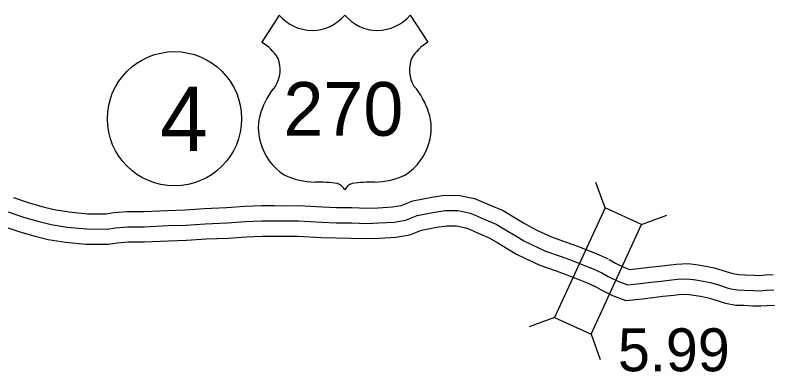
# Model space of a CAD drawing. Extents: x -83719 to 153526, y -11835 to 11446.
# Drawn here: x -4104.1 to -3856.7, y -3407.1 to -3290.1 of the extents above; entities that cross this region are included whole.
import ezdxf

# ---------------------------------------------------------------- set-up
doc = ezdxf.new("R2010")
doc.units = 0
for name, color, linetype in [('Level 15', 7, 'Continuous'), ('Level 20', 7, 'Continuous'), ('Level 22', 7, 'Continuous'), ('Level 27', 7, 'Continuous'), ('Level 58', 7, 'Continuous'), ('Level 59', 7, 'Continuous')]:
    doc.layers.add(name, color=color, linetype=linetype)

msp = doc.modelspace()

# ---------------------------------------------------------------- linework, layer by layer
at = {"layer": 'Level 15'}
for points in [[(-4104.59, -3349.95), (-4099.83, -3351.58), (-4095.29, -3352.89), (-4091.28, -3353.89), (-4086.33, -3354.67), (-4080.34, -3355.25), (-4074.22, -3355.26), (-4071.75, -3354.9), (-4067.46, -3354.51), (-4061.85, -3354.51), (-4054.13, -3354.15), (-4048.36, -3353.97), (-4042.06, -3353.53), (-4034.84, -3353.23), (-4028.8, -3352.79), (-4023.32, -3352.58), (-4019.07, -3352.6), (-4015.79, -3352.62), (-4011.11, -3352.59), (-4003.35, -3353), (-3998.76, -3353.2), (-3993.72, -3353.24), (-3988.81, -3353.41), (-3985.08, -3353.3), (-3980.44, -3353.02), (-3977.56, -3352.51), (-3973.78, -3350.98), (-3967.48, -3349.79), (-3963.35, -3349.21), (-3958.35, -3349.23), (-3953.54, -3350.3), (-3951.43, -3351.09), (-3948.43, -3352.42), (-3944.19, -3354.19), (-3940.79, -3356.24), (-3937.43, -3358.25), (-3934.94, -3359.71), (-3932.71, -3360.86), (-3928.36, -3362.86), (-3923.48, -3364.59), (-3919.79, -3365.91), (-3916.24, -3367.29), (-3912.71, -3368.67), (-3909.76, -3370.03)], [(-4108.06, -3359.33), (-4102.84, -3361.12), (-4097.89, -3362.55), (-4093.27, -3363.7), (-4087.59, -3364.59), (-4080.84, -3365.25), (-4073.49, -3365.27), (-4070.57, -3364.83), (-4067.01, -3364.51), (-4061.61, -3364.51), (-4053.75, -3364.14), (-4047.86, -3363.96), (-4041.5, -3363.51), (-4034.27, -3363.22), (-4028.25, -3362.78), (-4023.14, -3362.58), (-4019.12, -3362.6), (-4015.8, -3362.62), (-4011.35, -3362.6), (-4003.83, -3362.99), (-3999.02, -3363.2), (-3993.92, -3363.24), (-3988.83, -3363.41), (-3984.63, -3363.29), (-3979.28, -3362.97), (-3974.78, -3362.18), (-3970.94, -3360.62), (-3965.86, -3359.66), (-3962.67, -3359.21), (-3959.47, -3359.22), (-3956.39, -3359.91), (-3955.22, -3360.35), (-3952.39, -3361.61), (-3948.72, -3363.14), (-3945.94, -3364.82), (-3942.52, -3366.86), (-3939.77, -3368.47), (-3937.1, -3369.85), (-3932.13, -3372.14), (-3926.83, -3374.01), (-3923.28, -3375.28), (-3919.87, -3376.6), (-3916.63, -3377.87), (-3913.95, -3379.11)], [(-3909.36, -3370.24), (-3907.32, -3371.41), (-3904.4, -3372.9), (-3902.71, -3373.5), (-3899.75, -3373.18), (-3896.29, -3372.77), (-3892.96, -3372.39), (-3889.45, -3371.98), (-3887.38, -3371.73), (-3883.55, -3371.6), (-3880.28, -3371.99), (-3877.72, -3372.43), (-3875.02, -3372.96), (-3872.15, -3373.81), (-3868.92, -3374.87), (-3866.89, -3375.22), (-3864.84, -3375.28), (-3861.94, -3375.44), (-3860.05, -3375.47), (-3858.33, -3375.33), (-3855.68, -3375.19)], [(-3914.35, -3378.9), (-3912.09, -3380.21), (-3908.37, -3382.1), (-3903.9, -3383.69), (-3898.61, -3383.11), (-3895.14, -3382.7), (-3891.82, -3382.32), (-3888.27, -3381.91), (-3886.61, -3381.71), (-3883.98, -3381.62), (-3881.71, -3381.89), (-3879.52, -3382.27), (-3877.41, -3382.68), (-3875.14, -3383.36), (-3871.33, -3384.61), (-3867.88, -3385.19), (-3865.27, -3385.27), (-3862.3, -3385.44), (-3859.72, -3385.48), (-3857.65, -3385.31), (-3855.29, -3385.18)]]:
    msp.add_lwpolyline(points, dxfattribs=at)
at = {"layer": 'Level 20'}
for p, q in [((-3910.76, -3353.27), (-3913.81, -3345.02)), ((-3898.77, -3358.8), (-3890.52, -3355.75)), ((-3927.34, -3389.23), (-3935.59, -3392.28)), ((-3915.35, -3394.76), (-3912.31, -3403.02))]:
    msp.add_line(p, q, dxfattribs=at)
msp.add_lwpolyline([(-3910.76, -3353.27), (-3927.34, -3389.23), (-3915.35, -3394.76), (-3898.77, -3358.8)], close=True, dxfattribs=at)
at = {"layer": 'Level 22'}
for p, q in [((-4017.49, -3290.15), (-4023.26, -3299.07)), ((-3974.6, -3290.15), (-3968.83, -3299.07))]:
    msp.add_line(p, q, dxfattribs=at)
for centre, radius, start, end in [((-4006.75, -3281.11), 14.04, 220.075, 319.6701), ((-3985.34, -3281.11), 14.04, 220.3299, 319.925), ((-4030.8, -3312.02), 14.99, 30.7809, 59.9883), ((-3961.29, -3312.02), 14.99, 120.0117, 149.2191), ((-4027.5, -3308.07), 10.28, 328.8105, 21.2108), ((-3964.59, -3308.07), 10.28, 158.7892, 211.1895), ((-4000.63, -3329.13), 23.97, 138.9565, 162.6913), ((-3991.46, -3329.13), 23.97, 17.3087, 41.0435), ((-4008.55, -3327.17), 15.84, 160.9576, 197.3819), ((-3983.54, -3327.17), 15.84, 342.6181, 19.0424), ((-4005.97, -3327.12), 18.33, 195.1074, 237.1312), ((-3986.12, -3327.12), 18.33, 302.8688, 344.8926), ((-4005.63, -3321.35), 23.53, 244.0771, 269.5779), ((-3986.46, -3321.35), 23.53, 270.4221, 295.9229), ((-4005.08, -3387.99), 43.11, 81.1942, 90.9539), ((-3999.69, -3349.34), 4.13, 28.0342, 72.9864), ((-3992.4, -3349.34), 4.13, 107.0136, 151.9658), ((-3987.01, -3387.99), 43.11, 89.0461, 98.8058)]:
    msp.add_arc(centre, radius, start, end, dxfattribs=at)
at = {"layer": 'Level 27'}
msp.add_circle((-4051.84, -3324.13), 22, dxfattribs=at)
at = {"layer": 'Level 59'}
for points in [[(-4106.33, -3354.64), (-4101.34, -3356.35), (-4096.59, -3357.72), (-4092.27, -3358.8), (-4086.96, -3359.63), (-4080.59, -3360.25), (-4073.86, -3360.26), (-4071.16, -3359.86), (-4067.23, -3359.51), (-4061.73, -3359.51), (-4053.94, -3359.14), (-4048.11, -3358.97), (-4041.78, -3358.52), (-4034.55, -3358.23), (-4028.53, -3357.78), (-4023.23, -3357.58), (-4019.1, -3357.6), (-4015.8, -3357.62), (-4011.23, -3357.59), (-4003.59, -3358), (-3998.89, -3358.2), (-3993.82, -3358.24), (-3988.82, -3358.41), (-3984.86, -3358.29), (-3979.86, -3357.99), (-3976.17, -3357.35), (-3972.36, -3355.8), (-3966.67, -3354.72), (-3963.01, -3354.21), (-3958.91, -3354.22), (-3954.97, -3355.11), (-3953.33, -3355.72), (-3950.41, -3357.02), (-3946.45, -3358.67), (-3943.36, -3360.53), (-3939.97, -3362.55), (-3937.35, -3364.09), (-3934.9, -3365.36), (-3930.24, -3367.5), (-3925.15, -3369.3), (-3921.54, -3370.59), (-3918.05, -3371.95), (-3914.67, -3373.27), (-3911.86, -3374.57)], [(-3911.86, -3374.57), (-3909.71, -3375.81), (-3906.38, -3377.5), (-3903.3, -3378.6), (-3899.18, -3378.14), (-3895.72, -3377.73), (-3892.39, -3377.36), (-3888.86, -3376.94), (-3887, -3376.72), (-3883.76, -3376.61), (-3880.99, -3376.94), (-3878.62, -3377.35), (-3876.22, -3377.82), (-3873.64, -3378.58), (-3870.13, -3379.74), (-3867.39, -3380.21), (-3865.05, -3380.28), (-3862.12, -3380.44), (-3859.88, -3380.48), (-3857.99, -3380.32), (-3855.49, -3380.19)]]:
    msp.add_lwpolyline(points, dxfattribs=at)

# ---------------------------------------------------------------- texts
at = {"layer": 'Level 22'}
msp.add_text('270', height=17.6, dxfattribs=at).set_placement((-4016.13, -3329.7))
at = {"layer": 'Level 27'}
msp.add_text('4', height=21.12, dxfattribs=at).set_placement((-4056.57, -3334.69))
at = {"layer": 'Level 58'}
msp.add_text('5.99', height=14.08, dxfattribs=at).set_placement((-3906.55, -3406.89))

doc.saveas('drawing.dxf')
